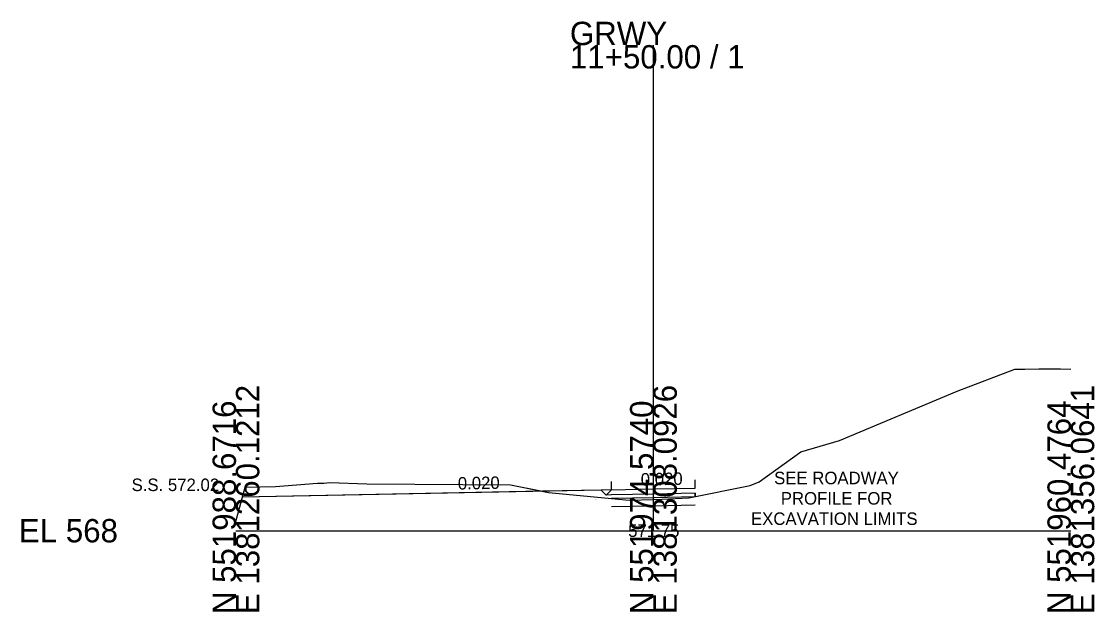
# Model space of a CAD drawing. Extents: x -26 to 103, y -10 to 3028.
# Drawn here: x -25.7 to 102.8, y 1490.3 to 1561 of the extents above; entities that cross this region are included whole.
import ezdxf

# ---------------------------------------------------------------- set-up
doc = ezdxf.new("R2010")
doc.units = 0
for name, color, linetype in [('Exist Cross Section Cell', 7, 'Continuous'), ('Exist XS Center Line Elevation Label', 7, 'Continuous'), ('Exist XS Ground Line', 7, 'Continuous'), ('Prop XS Dump Level', 7, 'Continuous'), ('Prop XS Earthwork Shape', 7, 'Continuous'), ('Prop XS EOT Tick Mark', 7, 'Continuous'), ('Prop XS Finish Grade', 7, 'Continuous'), ('Prop XS Finish Grade Earthwork', 7, 'Continuous'), ('Prop XS Finish Grade Pavement', 7, 'Continuous'), ('Prop XS Pvmt Edge Slope', 7, 'Continuous'), ('Prop XS SE Text', 7, 'Continuous'), ('Prop XS SS Elevation Text', 7, 'Continuous'), ('Prop XS Subgrade Earthwork', 7, 'Continuous'), ('Prop XSC Text', 7, 'Continuous')]:
    doc.layers.add(name, color=color, linetype=linetype)

msp = doc.modelspace()

# ---------------------------------------------------------------- linework, layer by layer
at = {"layer": 'Exist Cross Section Cell'}
for p, q in [((50, 1500), (50, 1558.21)), ((0, 1500), (50, 1500)), ((50, 1500), (100, 1500))]:
    msp.add_line(p, q, dxfattribs=at)
at = {"layer": 'Exist XS Ground Line'}
for p, q in [((86.37, 1516.73), (93.3, 1519.36)), ((93.3, 1519.36), (93.79, 1519.37)), ((93.79, 1519.37), (94.5, 1519.38)), ((94.5, 1519.38), (96.16, 1519.4)), ((96.16, 1519.4), (96.9, 1519.4)), ((96.9, 1519.4), (98.77, 1519.39)), ((98.77, 1519.39), (100, 1519.38)), ((72.31, 1510.8), (86.37, 1516.73)), ((67.67, 1509.47), (72.31, 1510.8)), ((62.68, 1505.87), (67.67, 1509.47)), ((0, 1501.11), (1.11, 1505.22)), ((1.11, 1505.22), (4.74, 1505.31)), ((4.74, 1505.31), (9.75, 1505.7)), ((9.75, 1505.7), (10.52, 1505.7)), ((10.52, 1505.7), (11.26, 1505.77)), ((11.26, 1505.77), (15.68, 1505.6)), ((15.68, 1505.6), (32.88, 1505.5)), ((32.88, 1505.5), (37.44, 1504.59)), ((54.26, 1503.94), (61.6, 1505.42)), ((61.6, 1505.42), (62.68, 1505.87)), ((37.44, 1504.59), (47.09, 1503.65)), ((51, 1503.79), (54.26, 1503.94)), ((47.09, 1503.65), (50, 1503.75)), ((50, 1503.75), (51, 1503.79))]:
    msp.add_line(p, q, dxfattribs=at)
at = {"layer": 'Prop XS Dump Level'}
for p, q in [((45, 1503.9), (50, 1504)), ((50, 1504), (55, 1504.1)), ((45, 1502.9), (50, 1503)), ((50, 1503), (55, 1503.1))]:
    msp.add_line(p, q, dxfattribs=at)
at = {"layer": 'Prop XS Earthwork Shape'}
for points in [[(10.52, 1505.7), (11.26, 1505.77), (15.68, 1505.6), (32.88, 1505.5), (36.73, 1504.73), (0.78, 1504.02), (1.11, 1505.22), (4.74, 1505.31), (9.75, 1505.7)], [(55, 1504.48), (50, 1504.38), (45, 1504.28), (44.36, 1504.26), (43.75, 1504.87), (36.73, 1504.73), (37.44, 1504.59), (47.09, 1503.65), (50, 1503.75), (51, 1503.79), (54.26, 1503.94), (55, 1504.09)]]:
    msp.add_lwpolyline(points, close=True, dxfattribs=at)
at = {"layer": 'Prop XS EOT Tick Mark'}
for p, q in [((45, 1504.9), (45, 1505.9)), ((55, 1505.1), (55, 1506.1))]:
    msp.add_line(p, q, dxfattribs=at)
at = {"layer": 'Prop XS Finish Grade'}
msp.add_line((45, 1504.9), (43.75, 1504.87), dxfattribs=at)
at = {"layer": 'Prop XS Finish Grade Earthwork'}
msp.add_line((43.75, 1504.87), (0.78, 1504.02), dxfattribs=at)
at = {"layer": 'Prop XS Finish Grade Pavement'}
for p, q in [((45, 1504.9), (50, 1505)), ((50, 1505), (55, 1505.1))]:
    msp.add_line(p, q, dxfattribs=at)
at = {"layer": 'Prop XS Pvmt Edge Slope'}
msp.add_line((45, 1504.9), (44.36, 1504.26), dxfattribs=at)
at = {"layer": 'Prop XS Subgrade Earthwork'}
for p, q in [((44.36, 1504.26), (43.75, 1504.87)), ((45, 1504.28), (44.36, 1504.26)), ((50, 1504.38), (45, 1504.28)), ((55, 1504.48), (50, 1504.38)), ((55, 1504.48), (55, 1504.09))]:
    msp.add_line(p, q, dxfattribs=at)

# ---------------------------------------------------------------- texts
at = {"layer": 'Exist Cross Section Cell'}
for s, p in [('GRWY', (40, 1558.21)), ('11+50.00 / 1', (40, 1555.41)), ('EL 568', (-26, 1498.6))]:
    msp.add_text(s, height=2.8, dxfattribs=at).set_placement(p)
for s, p in [('E 1381260.1212', (2.8, 1490)), ('E 1381308.0926', (52.8, 1490)), ('E 1381356.0641', (102.8, 1490)), ('N 551988.6716', (0, 1490)), ('N 551974.5740', (50, 1490)), ('N 551960.4764', (100, 1490))]:
    msp.add_text(s, height=2.8, rotation=90, dxfattribs=at).set_placement(p)
at = {"layer": 'Exist XS Center Line Elevation Label'}
msp.add_text('571.75', height=1.5, dxfattribs=at).set_placement((46.98, 1499.25))
at = {"layer": 'Prop XS Dump Level'}
for p in [(57, 1503.98), (43, 1503.7)]:
    msp.add_text('Case1', height=0.04, dxfattribs=at).set_placement(p)
at = {"layer": 'Prop XS SE Text'}
for p in [(26.59, 1504.92), (48.5, 1505.4)]:
    msp.add_text('0.020', height=1.5, rotation=1.1458, dxfattribs=at).set_placement(p)
at = {"layer": 'Prop XS SS Elevation Text'}
msp.add_text('S.S. 572.02', height=1.5, dxfattribs=at).set_placement((-12.5, 1504.75))
at = {"layer": 'Prop XSC Text'}
for s, p in [('SEE ROADWAY', (64.46, 1505.57)), ('PROFILE FOR', (65.26, 1503.13)), ('EXCAVATION LIMITS', (61.69, 1500.69))]:
    msp.add_text(s, height=1.5, dxfattribs=at).set_placement(p)

doc.saveas('drawing.dxf')
